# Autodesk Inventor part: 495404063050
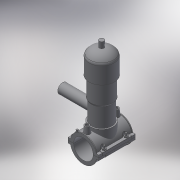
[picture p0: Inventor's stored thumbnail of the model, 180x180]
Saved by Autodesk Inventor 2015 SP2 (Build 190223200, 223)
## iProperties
Created: 2017-07
Part Number: 495404063050
Material: Generic
Description: PLASSON TAPPING VALVE 63-50
Document SubType Name: Modeling
Designer: KIM
Density: 1 g/cm^3
Appearance: Default
Author: KIM
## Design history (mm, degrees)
derived "495404-4954S4.ipt"
feature "Solid1::495404-4954S4.ipt"
feature "Solid2::495404-4954S4.ipt"
tag "TaggingFeature1"
body "Solid1"
body "Solid2"
other parameters: "d_" = 63, "B_" = 99, "H_" = 152, "L_" = 118, "d_t" = 6, "H_1" = 51, "H_2" = 244, "d148" = 0.945, "d160" = 0.945, "d169" = 3, "d192" = 6.8, "d0" = 63, "d2" = 99, "d3" = 15.75, "d4" = 118, "d5" = 0, "d6" = 0.1, "d8" = 0, "d19" = 6, "d20" = 6, "d21" = 70.8, "d23" = 0, "d24" = 35.4, "d26" = 0, "d27" = 3, "d28" = 3, "d29" = 3, "d30" = 21, "d31" = 6, "d32" = 0, "d33" = 0, "d34" = 0.6, "d40" = 42.588, "d47" = 91.95, "d70" = 15, "d72" = 0, "d73" = 6, "d75" = 5, "d76" = 0, "d77" = 3.15, "d78" = 61.5, "d79" = 15, "d80" = 47.2, "d82" = 5 deg, "d84" = 4, "d85" = 14, "d86" = 0, "d87" = 3, "d88" = 0, "d89" = 1, "d90" = 1, "d91" = 94.4, "d92" = 0, "d93" = 0.5, "d94" = 33.15789, "d96" = 84.357, "d97" = 2.36, "d98" = 0, "d120" = 140 deg, "d121" = 24.228, "d122" = 20 deg, "d123" = 163.8, "d124" = 49.14, "d126" = 0, "d143" = 64.89, "d145" = 14.53846, "d149" = 0.945, "d150" = 15.99231, "d153" = 118, "d154" = 0, "d156" = 40.95, "d157" = 160 deg, "d159" = 3.78, "d161" = 0.945, "d162" = 70.8, "d163" = 0, "d164" = 31.5, "d167" = 6.3, "d168" = 39.95122, "d170" = 3, "d172" = 0, "d173" = 1, "d175" = 31.5, "d176" = 20 deg, "d177" = 4.41, "d178" = 18.9, "d180" = 0, "d183" = 7.56, "d184" = 3.528, "d185" = 38.35, "d186" = 38.35, "d187" = 40.95, "d188" = 5.67, "d189" = 4.41, "d190" = 0, "d191" = 61.425, "d193" = 6.8, "d194" = 2.95, "d195" = 90 deg, "d197" = 0, "d199" = 0, "d205" = 14.64, "d206" = 81.33333, "d207" = 244, "d208" = 224.48, "d209" = 207.4, "d210" = 200.08, "d211" = 146.4, "d212" = 85.4, "d213" = 65.88, "d214" = 73.2, "d216" = 19.52, "d217" = 70.76, "d218" = 80.52, "d220" = 63, "d222" = 0, "d223" = 81.9, "d224" = 152, "d225" = 51, "d229" = 152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
